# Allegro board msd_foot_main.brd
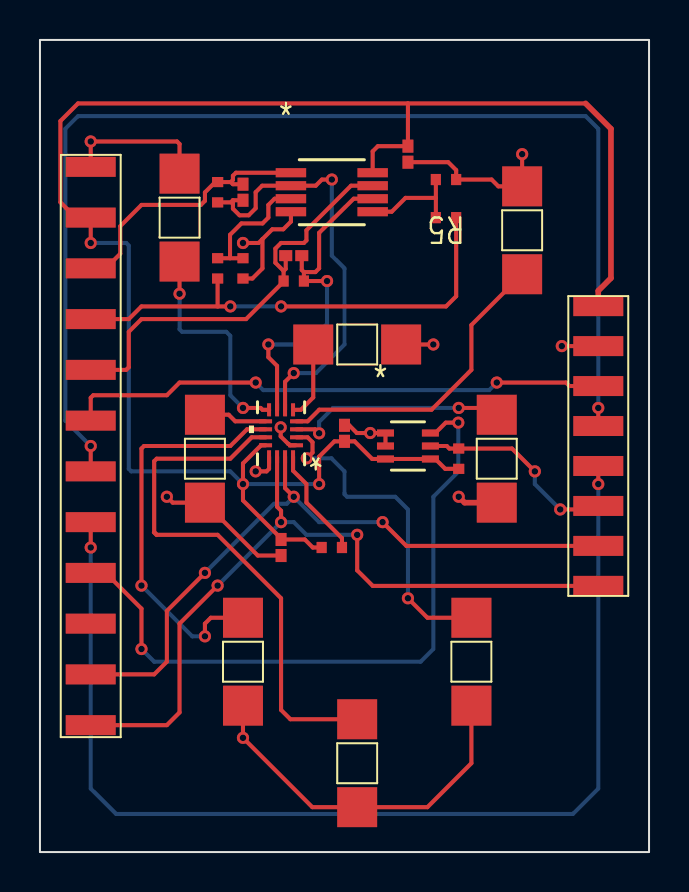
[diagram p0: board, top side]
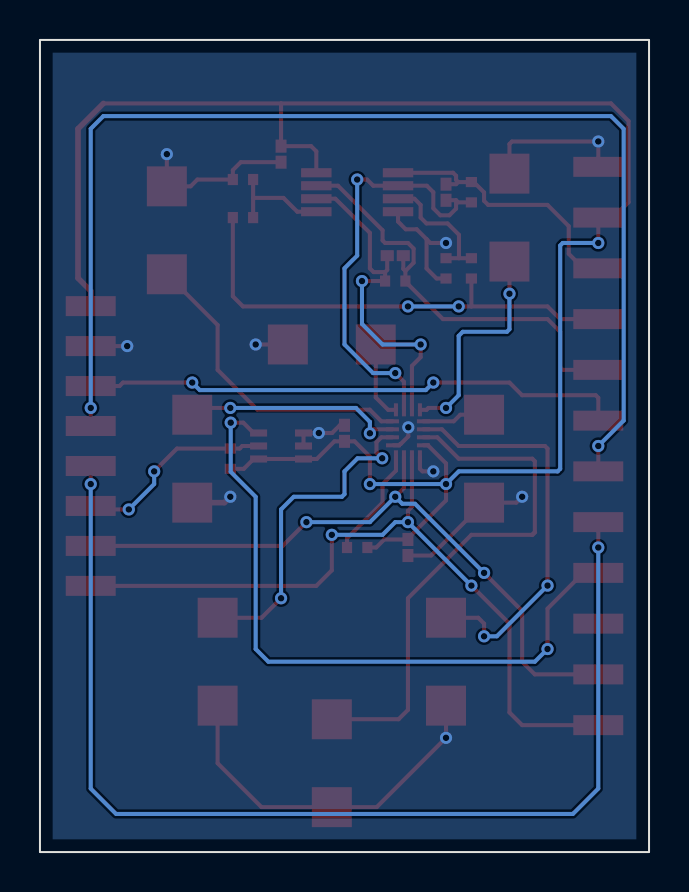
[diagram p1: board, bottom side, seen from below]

Outline 30.48 x 40.64 mm; copper layers: TOP, BOTTOM. Coordinates in mm from the lower left corner of the outline.
Outline path: rectangle 0,0 30.48,40.64

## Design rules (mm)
constraint set DEFAULT: min track width 0.127

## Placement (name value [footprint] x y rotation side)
C2  47pF  [CAPC10555_55N_KEM]  10.16 33.02 90 top
C3  47pF  [CAPC10555_55N_KEM]  12.7 29.84 180 top
C8  0.1uF  [CAPC10555_55N_KEM]  12.06 15.24 90 top
C9  0.1uF  [CAPC10555_55N_KEM]  15.24 20.96 270 top
C10  0.1uF  [CAPC10555_55N_KEM]  18.41 34.93 90 top
IO1  -  [EXT1_MAIN_CONNECTOR]  27.94 20.32 0 top
IO2  -  [MAIN_NANO_CONNECTOR]  2.54 20.32 0 top
R3  10k  [BO_CR0402]  8.89 29.21 90 top
R4  1k  [BO_CR0402]  10.16 29.21 270 top
R5  10k  [BO_CR0402]  20.32 31.75 180 top
R6  1k  [BO_CR0402]  20.32 33.66 0 top
R11  6.8k  [BO_CR0402]  8.89 33.02 90 top
R12  6.8k  [BO_CR0402]  12.7 28.58 180 top
R13  1k  [BO_CR0402]  14.6 15.24 180 top
R_SHUNT  1  [BO_CR0402]  20.96 19.69 270 top
SC1  Strain Cell  [STRAIN_CELL]  8.25 19.69 90 top
SC2  Strain Cell  [STRAIN_CELL]  10.16 9.53 90 top
SC3  Strain Cell  [STRAIN_CELL]  6.99 31.75 270 top
SC4  Strain Cell  [STRAIN_CELL]  15.88 4.44 90 top
SC5  Strain Cell  [STRAIN_CELL]  15.88 25.4 180 top
SC6  Strain Cell  [STRAIN_CELL]  24.13 31.12 270 top
SC7  Strain Cell  [STRAIN_CELL]  22.86 19.69 90 top
SC8  Strain Cell  [STRAIN_CELL]  21.59 9.53 90 top
U4  TMUX1109RSVR  [RSV16_TEX]  12.06 20.96 180 top
U5  MCP6002-IMS  [MSOP8_MC_MCH]  14.6 33.02 0 top
U13  INA212AIDCKTG4  [DCK6_TEX]  18.41 20.32 0 top

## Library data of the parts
C2 C3 = CAP NP
C8-C10 = C_1
IO1 = EXT1_MAIN_CONNECTOR
IO2 = MAIN_NANO_CONNECTOR
R3-R6 R11-R13 R_SHUNT = R
SC1-SC8 = Strain Cell
U4 = TMUX1109RSVR
U5 = MCP6002-IMS
U13 = INA212AIDCKT

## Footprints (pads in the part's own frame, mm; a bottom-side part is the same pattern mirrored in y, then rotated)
BO_CR0402
  rect 0.508x0.559 smd: 1(-0.508,0) 2(0.508,0)
CAPC10555_55N_KEM
  rect 0.653x0.55 smd: 1(-0.402,0) 2(0.402,0)
DCK6_TEX
  rect 0.851x0.356 smd: 1(-1.124,0.65) 2(-1.124,0) 3(-1.124,-0.65) 4(1.124,-0.65) 5(1.124,0) 6(1.124,0.65)
EXT1_MAIN_CONNECTOR
  rect 2.5x1 smd: 1(0,7) 2(0,5) 3(0,3) 4(0,1) 5(0,-1) 6(0,-3) 7(0,-5) 8(0,-7)
MAIN_NANO_CONNECTOR
  rect 2.5x1 smd: 1(0,13.97) 2(0,11.43) 3(0,8.89) 4(0,6.35) 5(0,3.81) 6(0,1.27) 7(0,-1.27) 8(0,-3.81) 9(0,-6.35) 10(0,-8.89) 11(0,-11.43) 12(0,-13.97)
MSOP8_MC_MCH
  rect 1.524x0.457 smd: 1(-2.045,0.975) 2(-2.045,0.325) 3(-2.045,-0.325) 4(-2.045,-0.975) 5(2.045,-0.975) 6(2.045,-0.325) 7(2.045,0.325) 8(2.045,0.975)
RSV16_TEX
  rect 0.75x0.2 smd: 1(-0.724,0.6)
  rect 0.65x0.2 smd: 2(-0.775,0.2) 3(-0.775,-0.2) 4(-0.775,-0.6) 9(0.775,-0.6) 10(0.775,-0.2) 11(0.775,0.2) 12(0.775,0.6)
  rect 0.2x0.65 smd: 5(-0.6,-1.175) 6(-0.2,-1.175) 7(0.2,-1.175) 8(0.6,-1.175) 13(0.6,1.175) 14(0.2,1.175) 15(-0.2,1.175) 16(-0.6,1.175)
STRAIN_CELL
  rect 2x2 smd: 1(-2.2,0) 2(2.2,0)

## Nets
3V3: IO2.4 R3.1 R5.1
5V: C8.2 C9.2 C10.2 IO1.1(VDD) IO2.2 R13.2 R_SHUNT.2 U4.12 U5.8 U13.3(V+) U13.4
GND: C8.1 C9.1 C10.1 IO1.2 IO2.1 R4.2 R6.2 SC1.1 SC2.1 SC3.1 SC4.1 SC5.1 SC6.1 SC7.1 SC8.1 U4.1(VSS) U4.13 U5.4(VSS) U13.1 U13.2
CNC_DETECT: IO2.9(SENSE) U13.6
MUXA_CHA: C2.1 R11.1 U4.6 U5.2
MUXA_CHB: C3.1 R12.1 U4.7 U5.6
MUXA_OPA: C2.2 IO2.3 R11.2 U5.1
MUXA_OPB: C3.2 IO2.5 R12.2 U5.7
MUXA_SEL0: IO1.7 IO2.11 U4.15
MUXA_SEL1: IO1.8 IO2.12 U4.14
MUXA_VDA: R3.2 R4.1 U5.3
MUXA_VDB: R5.2 R6.1 U5.5
N22758: R13.1 U4.16
N22786: IO1.6 R_SHUNT.1 U13.5
N23680: IO1.3 IO2.6
N23684: IO1.4 IO2.7
N23688: IO1.5 IO2.8
N25546: SC8.2 U4.2
N25553: SC7.2 U4.3
N25560: SC6.2 U4.4
N25572: SC5.2 U4.5
N26104: SC4.2 U4.11
N26119: SC2.2 U4.10
N26131: SC1.2 U4.9
N26211: SC3.2 U4.8

Pads without a net: IO2 10

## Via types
v1: diameter 0.61, hole 0.33, TOP to BOTTOM, 44 vias

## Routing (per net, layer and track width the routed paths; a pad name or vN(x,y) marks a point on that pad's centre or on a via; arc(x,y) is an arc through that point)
3V3: length 24.1
  TOP w0.127: 8.86,28.7 R3.1
  TOP w0.203: R3.1 8.89,27.31 ; 8.89,27.31 5.08,27.31 4.44,26.67 IO2.4 ; 8.89,27.31 v1(9.53,27.31) ; v1(12.06,27.31) 20.32,27.31 20.83,27.81 R5.1
  BOTTOM w0.203: v1(9.53,27.31) v1(12.06,27.31)
5V: length 90.4
  TOP w0.127: C8.2 12.06,15.69
  TOP w0.203: U5.8 16.65,35.06 16.91,35.33 C10.2 18.41,37.47 ; v1(13.97,18.41) 13.97,19.79 14.74,20.55 C9.2 15.74,20.55 16.63,19.67 U13.3 U13.4 19.79,19.67 20.28,19.18 R_SHUNT.2 ; 18.41,37.47 1.91,37.47 1.02,36.58 1.02,32.52 1.79,31.75 IO2.2 v1(2.54,30.48) ; 18.41,37.47 27.31,37.47 ; R13.2 13.65,15.24 13.25,15.64 C8.2 ; 12.06,15.69 10.16,17.6 v1(10.16,18.41) 10.16,19.45 11.07,20.36 U4.12
  TOP w0.279: IO1.1 27.94,28.09 28.57,28.72 28.57,36.19 27.31,37.47
  BOTTOM w0.203: v1(2.54,30.48) 4.32,30.48 4.44,30.35 4.44,19.18 4.57,19.05 9.53,19.05 v1(10.16,18.41) v1(13.97,18.41)
GND: length 57.6
  TOP w0.203: 11.13,30.67 11.13,29.21 10.63,28.7 R4.2 ; 11.13,30.67 11.63,31.17 12.18,31.17 12.56,31.55 U5.4 ; 11.13,30.67 10.94,30.48 v1(10.16,30.48) ; v1(24.13,34.93) SC6.1 22.94,33.31 22.6,33.66 R6.2 20.83,34.12 20.43,34.52 C10.1 ; C8.1 10.9,14.84 SC1.1 6.64,17.49 v1(6.35,17.78) ; SC2.1 v1(10.16,5.72) 13.63,2.25 SC4.1 19.39,2.25 21.59,4.44 SC8.1 ; U4.13 11.47,19.18 11.34,19.05 v1(10.8,19.05) ; U13.2 U13.1 v1(16.52,20.97) 15.86,20.97 15.47,21.36 C9.1 ; SC5.1 v1(19.69,25.4) ; v1(12.05,21.25) 12.05,20.8 12.42,20.43 12.44,20.43 12.51,20.36 U4.1 ; IO1.2 v1(26.12,25.32) ; IO2.1 v1(2.54,35.56) 6.86,35.56 6.99,35.43 SC3.1
  TOP w0.279: SC7.1 21.25,17.49 v1(20.96,17.78)
CNC_DETECT: length 33.9
  TOP w0.203: U13.6 19.79,20.97 20.31,21.49 v1(20.93,21.49) ; IO2.9 3.29,13.97 5.08,12.18 v1(5.08,10.16)
  BOTTOM w0.203: v1(5.08,10.16) 5.72,9.53 19.05,9.53 19.69,10.16 19.69,17.78 20.93,19.03 v1(20.93,21.49)
MUXA_CHA: length 21.7
  TOP w0.203: R11.1 9.55,32.51 9.66,32.62 ; v1(12.7,23.97) 12.26,23.53 U4.6 ; 9.66,32.62 C2.1 ; 9.66,32.62 9.66,32.2 9.99,31.87 10.44,31.87 10.8,32.22 10.8,33.02 11.12,33.35 U5.2 13.8,33.35 14.11,33.66 v1(14.6,33.66)
  BOTTOM w0.203: v1(12.7,23.97) 13.81,23.97 15.24,25.4 15.24,29.21 14.6,29.85 v1(14.6,33.66)
MUXA_CHB: length 17.4
  TOP w0.203: v1(11.43,25.4) 11.43,24.77 11.87,24.33 U4.7 ; 13.21,29.02 R12.1 v1(14.37,28.58) ; 13.21,29.02 13.78,29.02 13.97,29.21 13.97,30.99 15.7,32.69 U5.6 ; 13.21,29.02 13.1,29.13 C3.1
  BOTTOM w0.203: v1(11.43,25.4) 13.34,25.4 14.37,26.43 v1(14.37,28.58)
MUXA_OPA: length 13.8
  TOP w0.203: IO2.3 3.29,29.21 4.02,29.94 4.02,31.32 5.08,32.38 8.05,32.38 8.25,32.59 8.25,33.01 8.77,33.53 R11.2 9.55,33.53 ; 9.55,33.53 9.66,33.63 9.66,33.84 9.81,34 U5.1 ; 9.55,33.53 9.66,33.42 C2.2
MUXA_OPB: length 21.6
  TOP w0.127: 12.19,28.55 R12.2
  TOP w0.203: IO2.5 4.32,24.13 4.44,24.26 4.44,26.03 5.08,26.67 10.31,26.67 12.19,28.55 ; C3.2 12.3,29.19 12.19,29.08 ; 12.19,29.08 R12.2 ; 12.19,29.08 11.78,29.49 11.78,30.2 12.06,30.48 13.21,30.48 13.34,30.61 13.34,31.12 15.57,33.35 U5.7
MUXA_SEL0: length 33.8
  TOP w0.203: v1(12.7,17.78) 12.26,18.22 U4.15 ; IO2.11 5.72,8.89 6.35,9.53 6.35,12.06 v1(8.25,13.97) ; v1(17.15,16.51) 18.33,15.32 IO1.7
  BOTTOM w0.203: v1(8.25,13.97) 11.71,17.43 12.35,17.43 v1(12.7,17.78) 13.97,16.51 v1(17.15,16.51)
MUXA_SEL1: length 37.9
  TOP w0.203: v1(15.88,15.88) 15.88,14.1 16.65,13.32 IO1.8 ; v1(8.89,13.34) 6.99,11.43 6.99,6.99 6.35,6.35 IO2.12 ; U4.14 11.87,17.28 12.06,17.08 v1(12.06,16.51)
  BOTTOM w0.203: v1(8.89,13.34) v1(12.06,16.51) 12.7,16.51 13.34,15.88 v1(15.88,15.88)
MUXA_VDA: length 6.6
  TOP w0.203: 9.51,29.72 R4.1 ; 9.51,29.72 R3.2 ; 9.51,29.72 9.51,30.89 10.08,31.46 11.14,31.46 11.43,31.75 11.43,32.38 11.74,32.69 U5.3
MUXA_VDB: length 5.4
  TOP w0.203: 19.81,32.74 18.29,32.74 17.6,32.04 U5.5 ; 19.81,32.74 R6.1 ; 19.81,32.74 R5.2
N22758: length 5.6
  TOP w0.203: U4.16 12.66,19.09 13.34,18.41 13.34,17.49 15.11,15.71 R13.1
N22786: length 10.2
  TOP w0.203: U13.5 20.36,20.32 20.49,20.19 R_SHUNT.1 23.62,20.19 v1(24.77,19.05) ; IO1.6 27.76,17.15 v1(26.03,17.15)
  BOTTOM w0.203: v1(24.77,19.05) 24.77,18.41 v1(26.03,17.15)
N23680: length 27.2
  TOP w0.203: IO2.6 2.54,22.73 2.67,22.86 6.35,22.86 6.99,23.5 v1(10.8,23.5) ; IO1.3 26.5,23.32 26.32,23.5 v1(22.86,23.5)
  BOTTOM w0.203: v1(22.86,23.5) 22.48,23.12 11.17,23.12 v1(10.8,23.5)
N23684: length 59.7
  TOP w0.203: v1(27.94,22.22) IO1.4 ; IO2.7 v1(2.54,20.32)
  BOTTOM w0.203: v1(2.54,20.32) 1.27,21.59 1.27,36.19 1.91,36.83 27.31,36.83 27.94,36.19 v1(27.94,22.22)
N23688: length 55.9
  TOP w0.203: v1(27.94,18.41) IO1.5 ; IO2.8 v1(2.54,15.24)
  BOTTOM w0.203: v1(2.54,15.24) 2.54,3.18 3.81,1.91 26.67,1.91 27.94,3.18 v1(27.94,18.41)
N25546: length 16.6
  TOP w0.203: U4.2 13.39,20.76 13.64,20.51 13.64,19.99 v1(13.35,19.7) ; v1(18.41,12.7) 19.39,11.72 SC8.2
  BOTTOM w0.203: v1(18.41,12.7) 18.41,17.15 17.78,17.78 15.37,17.78 15.24,17.91 15.24,19.05 14.59,19.7 v1(13.35,19.7)
N25553: length 11.1
  TOP w0.203: SC7.2 22.52,22.22 v1(20.96,22.22) ; v1(13.97,20.96) 13.77,21.15 U4.3
  BOTTOM w0.203: v1(13.97,20.96) 13.97,21.53 14.67,22.22 v1(20.96,22.22)
N25560: length 15.7
  TOP w0.203: U4.4 13.39,21.55 13.98,22.14 19.6,22.14 21.59,24.13 21.59,26.38 SC6.2
N25572: length 3.9
  TOP w0.203: U4.5 13.06,22.13 13.68,22.75 SC5.2
N26104: length 26.9
  TOP w0.203: 5.84,15.88 8.89,15.88 12.06,12.7 12.06,7.11 12.53,6.64 SC4.2 ; 5.72,16 5.72,19.56 5.84,19.69 9.53,19.69 10.6,20.76 U4.11
  TOP w0.229: 5.72,16 5.84,15.88
N26119: length 20.4
  TOP w0.203: v1(8.25,10.8) 8.25,11.43 8.55,11.72 SC2.2 ; v1(5.08,13.34) 5.08,20.19 5.21,20.32 9.53,20.32 10.36,21.15 U4.10
  BOTTOM w0.203: v1(8.25,10.8) 7.62,10.8 v1(5.08,13.34)
N26131: length 3.2
  TOP w0.203: SC1.2 9.45,21.88 9.78,21.55 U4.9
N26211: length 11.3
  TOP w0.203: U4.8 11.14,22.13 11.04,22.22 v1(10.16,22.22) ; SC3.2 v1(6.99,27.94)
  BOTTOM w0.203: v1(10.16,22.22) 9.53,22.86 9.53,25.83 9.32,26.03 7.11,26.03 6.99,26.16 v1(6.99,27.94)

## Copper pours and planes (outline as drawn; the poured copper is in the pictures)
GND on BOTTOM: 0.63,40 0.63,0.63 29.84,0.63 29.84,40
